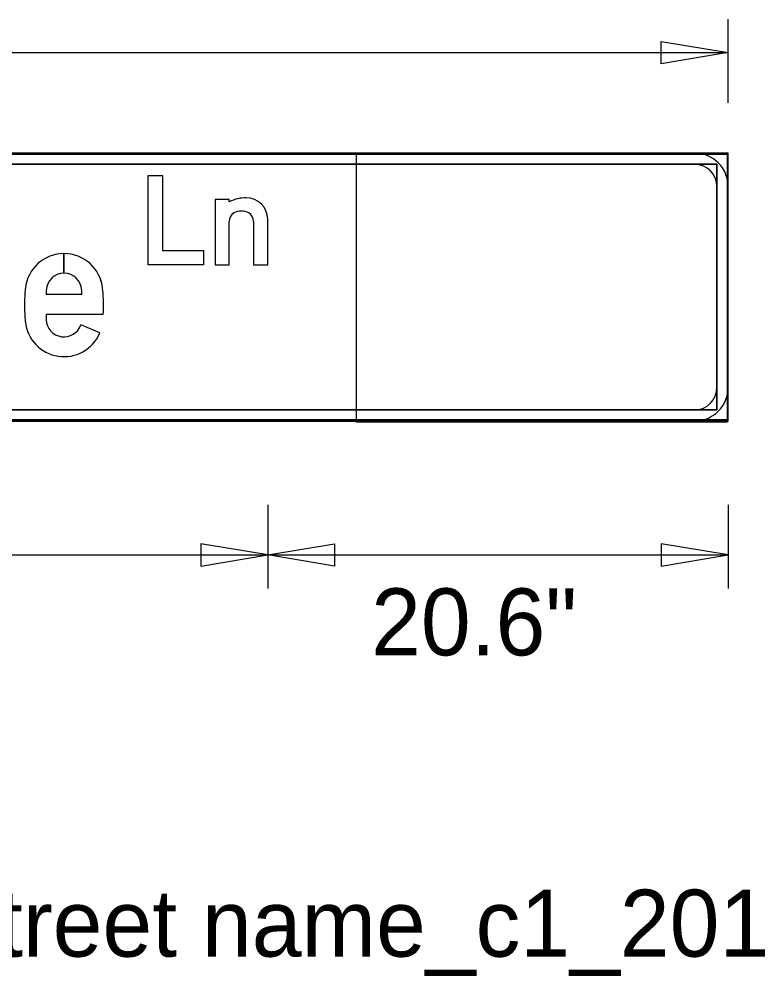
# Model space of a CAD drawing. Extents: x 1708.4 to 1771.6, y 238.3 to 283.4.
# Drawn here: x 1762.59 to 1765.906, y 249.581 to 253.872 of the extents above; entities that cross this region are included whole.
import ezdxf

# ---------------------------------------------------------------- set-up
doc = ezdxf.new("R2010")
doc.units = 0
for name, color, linetype in [('Level 11', 7, 'Continuous'), ('Level 2', 7, 'Continuous'), ('Level 3', 7, 'Continuous'), ('Level 4', 7, 'Continuous'), ('Level 5', 7, 'Continuous')]:
    doc.layers.add(name, color=color, linetype=linetype)

msp = doc.modelspace()

# ---------------------------------------------------------------- linework, layer by layer
at = {"layer": 'Level 11'}
msp.add_lwpolyline([(1764.1032, 253.2669), (1765.7635, 253.2669), (1765.7635, 252.0669), (1764.1032, 252.0669)], close=True, dxfattribs=at)
at = {"layer": 'Level 2'}
for p, q in [((1765.7685, 253.272), (1757.9683, 253.272)), ((1765.7685, 253.272), (1757.9683, 253.272)), ((1765.7685, 253.272), (1757.9683, 253.272)), ((1765.7685, 253.2719), (1757.9685, 253.2719)), ((1765.7685, 253.2719), (1757.9685, 253.2719)), ((1757.9732, 253.267), (1765.7635, 253.267)), ((1757.9735, 253.2669), (1765.7635, 253.2669)), ((1765.6185, 253.2719), (1758.1185, 253.2719)), ((1765.7635, 253.267), (1765.7635, 252.0765)), ((1765.7635, 253.2669), (1765.7635, 252.0766)), ((1765.7685, 252.0715), (1765.7685, 253.272)), ((1765.7685, 252.0715), (1765.7685, 253.272)), ((1765.7685, 252.0715), (1765.7685, 253.272)), ((1765.7685, 252.0716), (1765.7685, 253.2719)), ((1765.7685, 252.0716), (1765.7685, 253.2719)), ((1758.0183, 253.222), (1765.7185, 253.222)), ((1758.1185, 253.2219), (1765.6185, 253.2219)), ((1765.7185, 253.222), (1765.7185, 252.1215)), ((1765.7185, 253.1219), (1765.7185, 252.2216)), ((1765.7685, 252.2216), (1765.7685, 253.1219)), ((1763.6405, 252.9656), (1763.6405, 252.7719)), ((1762.7915, 252.7333), (1762.7915, 252.8218)), ((1762.7915, 252.8218), (1762.7915, 252.7333)), ((1762.8718, 252.6388), (1762.7112, 252.6388)), ((1762.711, 252.5503), (1762.9674, 252.5503)), ((1762.9518, 252.466), (1762.8668, 252.502)), ((1765.7185, 252.1215), (1757.9683, 252.1215)), ((1765.6185, 252.1216), (1758.119, 252.1216)), ((1765.7635, 252.0765), (1757.9683, 252.0765)), ((1757.9683, 252.0715), (1765.7685, 252.0715)), ((1757.9683, 252.0715), (1765.7685, 252.0715)), ((1757.9683, 252.0715), (1765.7685, 252.0715)), ((1765.7635, 252.0766), (1757.9685, 252.0766)), ((1757.9685, 252.0716), (1765.7685, 252.0716)), ((1757.9685, 252.0716), (1765.7685, 252.0716)), ((1758.119, 252.0716), (1765.6185, 252.0716))]:
    msp.add_line(p, q, dxfattribs=at)
msp.add_lwpolyline([(1763.2325, 252.8359), (1763.4165, 252.8359), (1763.4165, 252.7719), (1763.1685, 252.7719), (1763.1685, 253.1719), (1763.2325, 253.1719)], close=True, dxfattribs=at)
for points in [[(1763.5325, 253.0539), (1763.5325, 253.0639), (1763.4685, 253.0639), (1763.4685, 252.7719), (1763.5325, 252.7719), (1763.5325, 252.9656)], [(1763.6405, 252.7719), (1763.7045, 252.7719), (1763.7045, 252.9759)]]:
    msp.add_lwpolyline(points, dxfattribs=at)
for centre, radius, start, end in [((1765.6185, 253.1219), 0.15, 0, 90), ((1765.6185, 253.1219), 0.1, 0, 90), ((1763.6085, 252.9024), 0.1694, 90, 116.6491), ((1763.6085, 252.9759), 0.096, 0, 90), ((1763.5765, 252.967), 0.044, 123.3356, 181.7567), ((1763.5865, 252.9389), 0.0733, 62.2024, 117.7976), ((1763.5965, 252.967), 0.044, 358.2433, 56.6644), ((1765.6185, 252.2216), 0.15, 270, 0), ((1765.6185, 252.2216), 0.1, 270, 0)]:
    msp.add_arc(centre, radius, start, end, dxfattribs=at)
for centre, major_axis, start_param, end_param in [((1762.7915, 252.6476), (0, 0.1741), 0, 1.470576), ((1762.7915, 252.6476), (0, 0.1741), 4.81261, 6.283013), ((1762.7915, 252.6535), (0, 0.0797), 0, 1.530173), ((1762.7915, 252.6535), (0, 0.0797), 4.753012, 6.282809), ((1763.3568, 252.5908), (0, 0.7424), 1.470576, 1.570796), ((1764.3359, 252.5908), (0, 1.6255), 1.530173, 1.541262), ((1761.247, 252.5908), (0, 1.6255), 4.741924, 4.753012), ((1762.2261, 252.5908), (0, 0.7424), 4.712389, 4.81261), ((1763.3568, 252.5908), (0, 0.7424), 1.570796, 1.671017), ((1762.2261, 252.5908), (0, 0.7424), 4.657806, 4.712389), ((1764.3359, 252.5908), (0, 1.6255), 1.595715, 1.61142), ((1762.7915, 252.5339), (0, 0.1741), 1.671017, 4.311605), ((1762.7915, 252.528), (0, 0.0797), 1.61142, 4.380076)]:
    msp.add_ellipse(centre, major_axis=major_axis, ratio=0.999992, start_param=start_param, end_param=end_param, dxfattribs=at)
at = {"layer": 'Level 3'}
for p, q in [((1765.7685, 253.272), (1757.9683, 253.272)), ((1765.7685, 253.272), (1757.9683, 253.272)), ((1765.7685, 253.2719), (1757.9685, 253.2719)), ((1765.6185, 253.2719), (1758.1185, 253.2719)), ((1765.7685, 252.0715), (1765.7685, 253.272)), ((1765.7685, 252.0715), (1765.7685, 253.272)), ((1765.7685, 252.0716), (1765.7685, 253.2719)), ((1765.7185, 253.222), (1758.0183, 253.222)), ((1765.6185, 253.2219), (1758.1185, 253.2219)), ((1765.7185, 252.1215), (1765.7185, 253.222)), ((1765.7185, 252.2216), (1765.7185, 253.1219)), ((1765.7685, 252.2216), (1765.7685, 253.1219)), ((1763.6405, 252.9656), (1763.6405, 252.7719)), ((1762.8718, 252.6388), (1762.7112, 252.6388)), ((1762.711, 252.5503), (1762.9674, 252.5503)), ((1762.9518, 252.466), (1762.8668, 252.502)), ((1762.8668, 252.502), (1762.8668, 252.502)), ((1758.0183, 252.1215), (1765.7185, 252.1215)), ((1758.1185, 252.1216), (1765.6185, 252.1216)), ((1757.9683, 252.0715), (1765.7685, 252.0715)), ((1757.9683, 252.0715), (1765.7685, 252.0715)), ((1757.9685, 252.0716), (1765.7685, 252.0716)), ((1758.1185, 252.0716), (1765.6185, 252.0716))]:
    msp.add_line(p, q, dxfattribs=at)
msp.add_lwpolyline([(1763.2325, 252.8359), (1763.4165, 252.8359), (1763.4165, 252.7719), (1763.1685, 252.7719), (1763.1685, 253.1719), (1763.2325, 253.1719)], close=True, dxfattribs=at)
for points in [[(1763.5325, 253.0539), (1763.5325, 253.0639), (1763.4685, 253.0639), (1763.4685, 252.7719), (1763.5325, 252.7719), (1763.5325, 252.9656)], [(1763.6405, 252.7719), (1763.7045, 252.7719), (1763.7045, 252.9759)]]:
    msp.add_lwpolyline(points, dxfattribs=at)
for centre, radius, start, end in [((1765.6185, 253.1219), 0.15, 0, 90), ((1765.6185, 253.1219), 0.1, 0, 90), ((1763.6085, 252.9024), 0.1694, 90, 116.6491), ((1763.6085, 252.9759), 0.096, 0, 90), ((1763.5765, 252.967), 0.044, 123.3356, 181.7567), ((1763.5865, 252.9389), 0.0733, 62.2024, 117.7976), ((1763.5965, 252.967), 0.044, 358.2433, 56.6644), ((1765.6185, 252.2216), 0.15, 270, 0), ((1765.6185, 252.2216), 0.1, 270, 0)]:
    msp.add_arc(centre, radius, start, end, dxfattribs=at)
for centre, major_axis, start_param, end_param in [((1762.7915, 252.6476), (0, 0.1741), 4.81261, 7.753761), ((1762.7915, 252.6535), (0, 0.0797), 4.753012, 7.813358), ((1763.3568, 252.5908), (0, 0.7424), 1.470576, 1.570796), ((1764.3359, 252.5908), (0, 1.6255), 1.530173, 1.541262), ((1761.247, 252.5908), (0, 1.6255), 4.741924, 4.753012), ((1762.2261, 252.5908), (0, 0.7424), 4.712389, 4.81261), ((1763.3568, 252.5908), (0, 0.7424), 1.570796, 1.671017), ((1762.2261, 252.5908), (0, 0.7424), 4.657806, 4.712389), ((1764.3359, 252.5908), (0, 1.6255), 1.595715, 1.61142), ((1762.7915, 252.5339), (0, 0.1741), 1.671017, 4.311605), ((1762.7915, 252.528), (0, 0.0797), 1.61142, 4.380076)]:
    msp.add_ellipse(centre, major_axis=major_axis, ratio=0.999992, start_param=start_param, end_param=end_param, dxfattribs=at)
at = {"layer": 'Level 4'}
for p, q in [((1765.7685, 253.272), (1757.9683, 253.272)), ((1765.7685, 253.272), (1757.9683, 253.272)), ((1765.7685, 253.2719), (1757.9685, 253.2719)), ((1765.6185, 253.2719), (1758.1185, 253.2719)), ((1765.7685, 252.0715), (1765.7685, 253.272)), ((1765.7685, 252.0715), (1765.7685, 253.272)), ((1765.7685, 252.0716), (1765.7685, 253.2719)), ((1758.0183, 253.222), (1765.7185, 253.222)), ((1758.1185, 253.2219), (1765.6185, 253.2219)), ((1765.7185, 253.222), (1765.7185, 252.1215)), ((1765.7185, 253.1219), (1765.7185, 252.2216)), ((1765.7685, 252.2216), (1765.7685, 253.1219)), ((1763.6405, 252.9656), (1763.6405, 252.7719)), ((1762.7915, 252.7333), (1762.7915, 252.8218)), ((1762.7915, 252.8218), (1762.7915, 252.7333)), ((1762.8718, 252.6388), (1762.7112, 252.6388)), ((1762.711, 252.5503), (1762.9674, 252.5503)), ((1762.9518, 252.466), (1762.8668, 252.502)), ((1765.7185, 252.1215), (1757.9683, 252.1215)), ((1765.6185, 252.1216), (1758.119, 252.1216)), ((1757.9683, 252.0715), (1765.7685, 252.0715)), ((1757.9683, 252.0715), (1765.7685, 252.0715)), ((1757.9685, 252.0716), (1765.7685, 252.0716)), ((1758.119, 252.0716), (1765.6185, 252.0716))]:
    msp.add_line(p, q, dxfattribs=at)
msp.add_lwpolyline([(1763.2325, 252.8359), (1763.4165, 252.8359), (1763.4165, 252.7719), (1763.1685, 252.7719), (1763.1685, 253.1719), (1763.2325, 253.1719)], close=True, dxfattribs=at)
for points in [[(1763.5325, 253.0539), (1763.5325, 253.0639), (1763.4685, 253.0639), (1763.4685, 252.7719), (1763.5325, 252.7719), (1763.5325, 252.9656)], [(1763.6405, 252.7719), (1763.7045, 252.7719), (1763.7045, 252.9759)]]:
    msp.add_lwpolyline(points, dxfattribs=at)
for centre, radius, start, end in [((1765.6185, 253.1219), 0.15, 0, 90), ((1765.6185, 253.1219), 0.1, 0, 90), ((1763.6085, 252.9024), 0.1694, 90, 116.6491), ((1763.6085, 252.9759), 0.096, 0, 90), ((1763.5765, 252.967), 0.044, 123.3356, 181.7567), ((1763.5865, 252.9389), 0.0733, 62.2024, 117.7976), ((1763.5965, 252.967), 0.044, 358.2433, 56.6644), ((1765.6185, 252.2216), 0.15, 270, 0), ((1765.6185, 252.2216), 0.1, 270, 0)]:
    msp.add_arc(centre, radius, start, end, dxfattribs=at)
for centre, major_axis, start_param, end_param in [((1762.7915, 252.6476), (0, 0.1741), 0, 1.470576), ((1762.7915, 252.6476), (0, 0.1741), 4.81261, 6.283013), ((1762.7915, 252.6535), (0, 0.0797), 0, 1.530173), ((1762.7915, 252.6535), (0, 0.0797), 4.753012, 6.282809), ((1763.3568, 252.5908), (0, 0.7424), 1.470576, 1.570796), ((1764.3359, 252.5908), (0, 1.6255), 1.530173, 1.541262), ((1761.247, 252.5908), (0, 1.6255), 4.741924, 4.753012), ((1762.2261, 252.5908), (0, 0.7424), 4.712389, 4.81261), ((1763.3568, 252.5908), (0, 0.7424), 1.570796, 1.671017), ((1762.2261, 252.5908), (0, 0.7424), 4.657806, 4.712389), ((1764.3359, 252.5908), (0, 1.6255), 1.595715, 1.61142), ((1762.7915, 252.5339), (0, 0.1741), 1.671017, 4.311605), ((1762.7915, 252.528), (0, 0.0797), 1.61142, 4.380076)]:
    msp.add_ellipse(centre, major_axis=major_axis, ratio=0.999992, start_param=start_param, end_param=end_param, dxfattribs=at)
at = {"layer": 'Level 5'}
for p, q in [((1765.7687, 253.497), (1765.7687, 253.872)), ((1757.9683, 253.722), (1765.7687, 253.722)), ((1765.7687, 253.497), (1765.7687, 253.497)), ((1763.7045, 251.6965), (1763.7045, 251.3215)), ((1763.7045, 251.6965), (1763.7045, 251.3215)), ((1765.7687, 251.6965), (1765.7687, 251.3215)), ((1765.7687, 251.6965), (1765.7687, 251.3215)), ((1758.1685, 251.4715), (1763.7045, 251.4715)), ((1763.7045, 251.4715), (1765.7687, 251.4715))]:
    msp.add_line(p, q, dxfattribs=at)
for points in [[(1765.7687, 253.722), (1765.4688, 253.672), (1765.4688, 253.772)], [(1763.7045, 251.4715), (1763.4045, 251.5215), (1763.4045, 251.4215)], [(1763.7045, 251.4715), (1764.0045, 251.5215), (1764.0045, 251.4215)], [(1765.7687, 251.4715), (1765.4688, 251.5215), (1765.4688, 251.4215)]]:
    msp.add_lwpolyline(points, close=True, dxfattribs=at)

# ---------------------------------------------------------------- texts
for s, p in [('20.6"', (1764.1684, 251.0215)), ('Panel Style: guide_con_street name_c1_2012.ssi', (1757.9683, 249.6715))]:
    msp.add_text(s, height=0.3, dxfattribs=at).set_placement(p)

doc.saveas('drawing.dxf')
